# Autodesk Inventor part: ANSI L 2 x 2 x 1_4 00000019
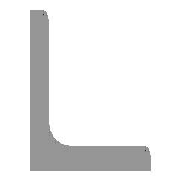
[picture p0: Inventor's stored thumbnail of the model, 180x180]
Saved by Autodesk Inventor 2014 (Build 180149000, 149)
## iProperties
IsCustomPart: 1
Created: 2007-02
Part Number: ANSI L 2 x 2 x 1_4 00000019
Material: Steel, Mild
Document SubType Name: Modeling
Standard: AISC
Designer: Autodesk, Inc.
Size Designation: L 2 x 2 x 1/4
Stock Number: L 2 x 2 x 1/4
Density: 7.86 g/cm^3
Description: Angle Steel
Standards Organization: ANSI
Language: en-US
Categories: <MemberInstance><Categories><Category DisplayName="Structural Shapes" InternalName="089c4875-fa83-4c05-b084-43b9cc11f5ed" Mnemonic="GRDR"><CategoryParameter Dis
Mass: 3340.38 g
Surface Area: 1393.58 cm^2
Volume: 424.985 cm^3
Appearance: Steel
_FrameMemberDoc: Frame Member File
_Version: 15.0.0
_CCFamilyMember: 11
_CCFamilyDisplayName: ANSI L (Equal angles) - Angle Steel
G_L: 28.675 in
G_W: 2.000 in
G_H: 2.000 in
+D52C80DA-68A4-4CBB-9C6A-ACD6371EF90B+CUTDETAIL1: Cut
+2F602F3C-6FCA-498D-902F-8FA70BE274E3+CUTDETAIL2: Cut
+7A6A31D2-3E5C-428A-98C3-55D5419C809F+CUTDETAIL3: Notch
Author: Autodesk, Inc.
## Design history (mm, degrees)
node "Start plane"
node "End plane"
sketch "Sketch"
  geometry: L1 (50.8, 0)-(0, 0); L2 (0, 0)-(0, 50.8); L3 (0, 50.8)-(3.302, 50.8); L4 (6.35, 47.752)-(6.35, 12.7); L5 (12.7, 6.35)-(47.752, 6.35); L6 (50.8, 3.302)-(50.8, 0); L7 (0, -11.041)-(0, 31.538); L8 (-11.041, 0)-(31.538, 0); L9 (0, 63.926)-(0, -23.536) reference; L10 (-23.536, 0)-(63.926, 0) reference; A1 r 6.35 centre (12.7, 12.7) between (6.35, 12.7) and (12.7, 6.35); A2 r 3.048 centre (3.302, 47.752) between (6.35, 47.752) and (3.302, 50.8); A3 r 3.048 centre (47.752, 3.302) between (50.8, 3.302) and (47.752, 6.35); 3 further points
  constraints: 16 end point, 6 point on circle, 6 point on line, 6 tangent, 4 parallel, 3 centre point, 2 collinear, 1 equal radius, 1 horizontal, 1 perpendicular
  dimensions: "d0" = 50.8 distance between parallel lines of L6 L2 (= G_H); "d1" = 50.8 distance between parallel lines of L3 L1 (= G_H); "d2" = 6.35 distance between parallel lines of L2 L4 (= G_T); "d3" = 6.35 distance between parallel lines of L1 L5 (= G_T); "d10" = 0 distance between parallel lines of L7 L2 (computed from ex); "d11" = 0 distance between parallel lines of L8 L1 (computed from d10); "d14" = 6.35 radius of A1 (= G_IR); "d15" = 3.048 radius of A2 (= G_ER)
extrude "Body" new body sketch "Sketch" stored distance "d4" = 728.33422 (= G_L); taper "d5" = 0 deg
node "Driven Length"
  sketch "Sketch4"
    geometry: L1 (0, 0)-(10, 0) reference
    constraints: 2 end point, 1 horizontal
  workplane "Work Plane7"
  sketch "Sketch5"
    geometry: L1 (-2, 13.493)-(12, 13.493) reference; L2 (-2, 741.827)-(12, 741.827) reference
    dimensions: "d19" = 728.33422 distance between parallel lines of L1 L2 (derived)
workplane "Work Plane3"
split "Split1"
workplane "Work Plane4"
split "Split2"
workplane "Work Plane5"
workplane "Work Plane6"
workplane "Work Plane8"
body "Solid1"
sketch "Sketch_1"
  geometry: L1 (50.8, 0)-(0, 0); L2 (0, 0)-(0, 50.8); L3 (0, 50.8)-(3.302, 50.8); L4 (6.35, 47.752)-(6.35, 12.7); L5 (12.7, 6.35)-(47.752, 6.35); L6 (50.8, 3.302)-(50.8, 0); A1 r 3.048 centre (3.302, 47.752) between (6.35, 47.752) and (3.302, 50.8); A2 r 6.35 centre (12.7, 12.7) between (6.35, 12.7) and (12.7, 6.35); A3 r 3.048 centre (47.752, 3.302) between (50.8, 3.302) and (47.752, 6.35)
  constraints: 12 end point, 6 point on circle, 3 centre point
extrude "Extrusion2" cut sketch "Sketch_1" stored distance "d20" = 3.302; taper "d21" = 0 deg
other parameters: "G_H" = 50.8 [user parameter; used in 2 equation terms], "G_T" = 6.35 [user parameter; used in 2 equation terms], "G_ER" = 3.048 [user parameter; used in 1 equation term], "G_IR" = 6.35 [user parameter; used in 1 equation term], "G_L" = 728.33422 (= d19) [user parameter; used in 1 equation term], "ex" = 0 [user parameter; used in 1 equation term], "G_OFFSET_START" = -13.49265 [user parameter; used in 1 equation term], "G_OFFSET_END" = 5.54156 [user parameter; used in 1 equation term], "d12" = 13.49265 (= -G_OFFSET_START), "d13" = 741.82687 (= G_OFFSET_END + B_L), "B_L" = 736.2853 [user parameter; used in 1 equation term], "d18" = 90 deg
